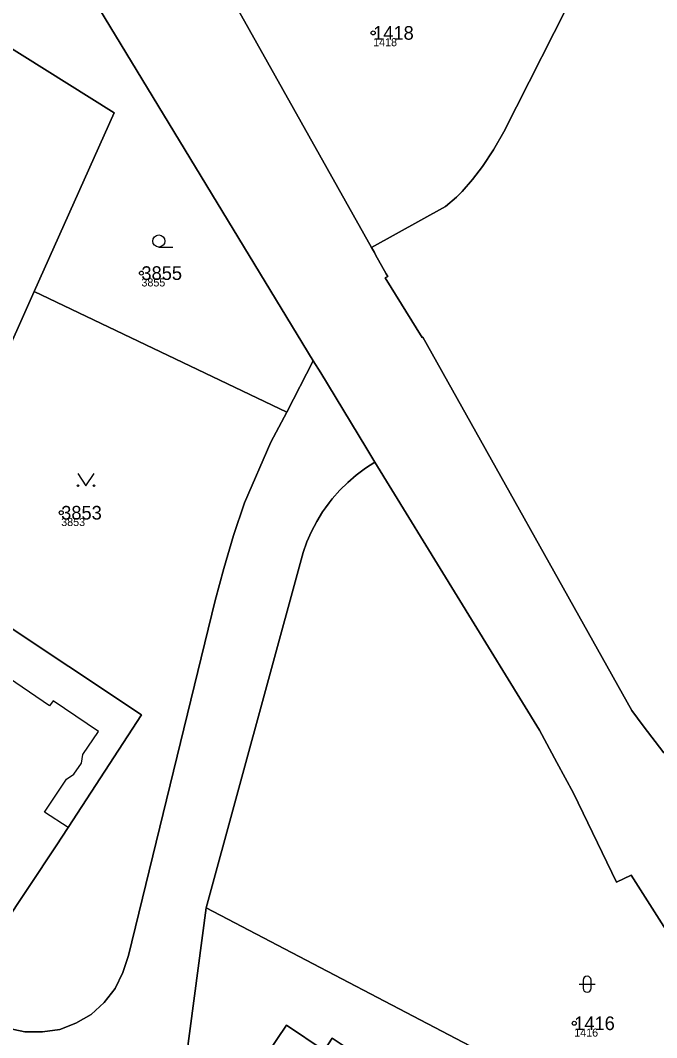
# Model space of a CAD drawing. Extents: x -690132 to -685994, y -975441 to -972444.
# Drawn here: x -688229.2 to -688149.9, y -974661.4 to -974534.7 of the extents above; entities that cross this region are included whole.
import ezdxf

# ---------------------------------------------------------------- set-up
doc = ezdxf.new("R2010")
doc.units = 0
for name, color, linetype in [('Definiční body', 7, 'Continuous'), ('Hranice parcel', 7, 'Continuous'), ('Parcelní čísla', 7, 'Continuous'), ('Polygon budovy', 7, 'Continuous'), ('Polygon parcely', 7, 'Continuous'), ('Vnitřní kresba', 7, 'Continuous'), ('Značky kultur', 7, 'Continuous')]:
    doc.layers.add(name, color=color, linetype=linetype)

msp = doc.modelspace()

# ---------------------------------------------------------------- linework, layer by layer
at = {"layer": 'Definiční body'}
for centre in [(-688185.26, -974536.23), (-688214.14, -974566.16), (-688224.14, -974596.01), (-688160.2, -974659.62)]:
    msp.add_circle(centre, 0.25, dxfattribs=at)
at = {"layer": 'Hranice parcel'}
for p, q in [((-688196.03, -974583.47), (-688227.51, -974568.46)), ((-688196.03, -974583.47), (-688192.72, -974577.08)), ((-688194.35, -974602.34), (-688206.07, -974645.24)), ((-688206.07, -974645.24), (-688210.5, -974678.74)), ((-688167.82, -974665.26), (-688206.07, -974645.24))]:
    msp.add_line(p, q, dxfattribs=at)
for points in [[(-688226.93, -974494.5), (-688226.36, -974494.84), (-688228.12, -974498.25), (-688227.56, -974498.86), (-688228.1, -974504.08), (-688228.16, -974504.63), (-688227.95, -974509.99), (-688227.92, -974510.85), (-688227.07, -974516.99), (-688225.82, -974521.31), (-688223.67, -974525.76), (-688219.35, -974533.29), (-688192.72, -974577.08)], [(-688214, -974502.8), (-688213.74, -974504.74), (-688206.25, -974525.92), (-688185.48, -974562.95)], [(-688185.48, -974562.95), (-688176.26, -974557.84), (-688174.87, -974556.7), (-688174.17, -974555.98), (-688172.87, -974554.48), (-688171.64, -974552.87), (-688170.27, -974550.8), (-688168.96, -974548.55), (-688159.56, -974529.9), (-688160.2, -974529.58)], [(-688227.51, -974568.46), (-688217.55, -974546.21), (-688234.6, -974535.5)], [(-688137.77, -974631.27), (-688139.27, -974630.74), (-688142.11, -974629.76), (-688143.26, -974629.15), (-688145.38, -974628.02), (-688146.53, -974627.41), (-688146.43, -974627.23), (-688149.02, -974625.93), (-688151.61, -974622.56), (-688153.01, -974620.67), (-688179.08, -974574.14), (-688179.17, -974574.19), (-688183.76, -974566.73), (-688183.45, -974566.56), (-688183.62, -974566.26), (-688184.95, -974563.9), (-688185.11, -974563.6), (-688185.48, -974562.95)], [(-688227.51, -974568.46), (-688236.79, -974589.17), (-688246.24, -974584.46), (-688250.35, -974592.63)], [(-688192.72, -974577.08), (-688191.79, -974578.6), (-688186.17, -974587.86), (-688185.03, -974589.73)], [(-688246.03, -974650.73), (-688233.43, -974659.18), (-688232.89, -974659.47), (-688230.82, -974660.22), (-688228.67, -974660.69), (-688226.48, -974660.68), (-688224.32, -974660.38), (-688222.3, -974659.6), (-688220.4, -974658.52), (-688218.77, -974657.02), (-688217.43, -974655.28), (-688216.44, -974653.28), (-688215.74, -974651.18), (-688204.95, -974606.93), (-688203.89, -974602.95), (-688202.67, -974598.84), (-688201.3, -974594.78), (-688198.01, -974587.21), (-688196.03, -974583.47)], [(-688185.03, -974589.73), (-688186.22, -974590.48), (-688187.36, -974591.32), (-688188.43, -974592.23), (-688189.43, -974593.22), (-688190.36, -974594.28), (-688190.75, -974594.76), (-688191.57, -974595.91), (-688192.3, -974597.11), (-688192.95, -974598.36), (-688193.51, -974599.65), (-688193.98, -974600.98), (-688194.35, -974602.34)], [(-688185.03, -974589.73), (-688164.51, -974623.1), (-688162.36, -974627.14), (-688160.29, -974630.96), (-688154.92, -974642.04), (-688153.12, -974641.17), (-688147, -974650.74), (-688144.11, -974656.03), (-688143.04, -974657.52), (-688141.72, -974658.88), (-688139.95, -974660.3), (-688138.04, -974661.53), (-688136.02, -974662.52), (-688077.82, -974683.21), (-688075.88, -974684.07), (-688073.68, -974685.3)], [(-688223.29, -974635.24), (-688214.14, -974621.2), (-688250.39, -974597.11)], [(-688246.03, -974650.73), (-688241.97, -974644.53), (-688241.77, -974644.24), (-688240.37, -974642.09), (-688240.05, -974642.22), (-688231.6, -974647.77), (-688224.78, -974637.53), (-688223.29, -974635.24)], [(-688177.47, -974678.89), (-688189.24, -974676.88), (-688193.95, -974673.72), (-688194.2, -974674.09), (-688197.45, -974671.92), (-688197.2, -974671.55), (-688201.85, -974668.42), (-688196.05, -974659.85), (-688191.36, -974663), (-688190.35, -974661.49), (-688187.14, -974663.63), (-688187.48, -974664.13), (-688185.57, -974665.45), (-688185.21, -974664.91), (-688182.5, -974666.73), (-688177.63, -974666.01)]]:
    msp.add_lwpolyline(points, dxfattribs=at)
at = {"layer": 'Polygon budovy'}
msp.add_lwpolyline([(-688231.6, -974647.77), (-688224.78, -974637.53), (-688223.29, -974635.24), (-688226.23, -974633.31), (-688223.49, -974629.19), (-688222.56, -974628.6), (-688221.63, -974627.21), (-688221.45, -974626.12), (-688219.5, -974623.25), (-688225.16, -974619.44), (-688225.58, -974620.06), (-688231.5, -974616.05)], dxfattribs=at)
msp.add_lwpolyline([(-688196.05, -974659.85), (-688201.85, -974668.42), (-688197.2, -974671.55), (-688197.45, -974671.92), (-688194.2, -974674.09), (-688193.95, -974673.72), (-688189.24, -974676.88), (-688187.37, -974674.06), (-688186.13, -974672.21), (-688184.65, -974669.99), (-688183.95, -974668.95), (-688183.5, -974668.25), (-688186.22, -974666.43), (-688185.57, -974665.45), (-688187.48, -974664.13), (-688187.14, -974663.63), (-688190.35, -974661.49), (-688191.36, -974663)], close=True, dxfattribs=at)
at = {"layer": 'Polygon parcely'}
for points in [[(-688174.87, -974556.7), (-688174.17, -974555.98), (-688172.87, -974554.48), (-688171.64, -974552.87), (-688170.27, -974550.8), (-688168.96, -974548.55), (-688159.56, -974529.9), (-688160.2, -974529.58), (-688166.78, -974526.32), (-688172.24, -974523.91), (-688188.89, -974516.57), (-688191.58, -974515.38), (-688196.43, -974512.57), (-688204.31, -974508), (-688211.75, -974503.7), (-688214, -974502.8), (-688213.74, -974504.74), (-688206.25, -974525.92), (-688185.48, -974562.95), (-688176.26, -974557.84)], [(-688235.32, -974536.94), (-688242.43, -974551.08), (-688246.59, -974559.36), (-688256.6, -974579.3), (-688248.38, -974583.39), (-688252.34, -974591.59), (-688250.35, -974592.63), (-688246.24, -974584.46), (-688236.79, -974589.17), (-688227.51, -974568.46), (-688217.55, -974546.21), (-688234.6, -974535.5)], [(-688172.31, -974669.14), (-688177.63, -974666.01), (-688182.5, -974666.73), (-688185.21, -974664.91), (-688185.57, -974665.45), (-688187.48, -974664.13), (-688187.14, -974663.63), (-688190.35, -974661.49), (-688191.36, -974663), (-688196.05, -974659.85), (-688201.85, -974668.42), (-688197.2, -974671.55), (-688197.45, -974671.92), (-688194.2, -974674.09), (-688193.95, -974673.72), (-688189.24, -974676.88), (-688177.47, -974678.89), (-688172.81, -974672.27)]]:
    msp.add_lwpolyline(points, close=True, dxfattribs=at)
for points in [[(-688134.02, -974533.98), (-688158.05, -974524.54), (-688159.47, -974527.87), (-688160.2, -974529.58), (-688159.56, -974529.9), (-688168.96, -974548.55), (-688170.27, -974550.8), (-688171.64, -974552.87), (-688172.87, -974554.48), (-688174.17, -974555.98), (-688174.87, -974556.7), (-688176.26, -974557.84), (-688185.48, -974562.95), (-688185.11, -974563.6), (-688184.95, -974563.9), (-688183.62, -974566.26), (-688183.45, -974566.56), (-688183.76, -974566.73), (-688179.17, -974574.19), (-688179.08, -974574.14), (-688153.01, -974620.67), (-688151.61, -974622.56), (-688149.02, -974625.93)], [(-688149.02, -974625.93), (-688151.61, -974622.56), (-688153.01, -974620.67), (-688179.08, -974574.14), (-688179.17, -974574.19), (-688183.76, -974566.73), (-688183.45, -974566.56), (-688183.62, -974566.26), (-688184.95, -974563.9), (-688185.11, -974563.6), (-688185.48, -974562.95), (-688206.25, -974525.92)], [(-688244.23, -974528.29), (-688257.52, -974554.15), (-688253.8, -974555.92), (-688246.59, -974559.36), (-688242.43, -974551.08), (-688235.32, -974536.94), (-688234.6, -974535.5), (-688217.55, -974546.21), (-688227.51, -974568.46), (-688196.03, -974583.47), (-688192.72, -974577.08), (-688219.35, -974533.29)], [(-688219.35, -974533.29), (-688192.72, -974577.08), (-688191.79, -974578.6), (-688186.17, -974587.86), (-688185.03, -974589.73), (-688164.51, -974623.1), (-688162.36, -974627.14), (-688160.29, -974630.96), (-688154.92, -974642.04), (-688153.12, -974641.17), (-688147, -974650.74)], [(-688230.82, -974660.22), (-688228.67, -974660.69), (-688226.48, -974660.68), (-688224.32, -974660.38), (-688222.3, -974659.6), (-688220.4, -974658.52), (-688218.77, -974657.02), (-688217.43, -974655.28), (-688216.44, -974653.28), (-688215.74, -974651.18), (-688204.95, -974606.93), (-688203.89, -974602.95), (-688202.67, -974598.84), (-688201.3, -974594.78), (-688198.01, -974587.21), (-688196.03, -974583.47), (-688227.51, -974568.46), (-688236.79, -974589.17)], [(-688210.5, -974678.74), (-688206.07, -974645.24), (-688194.35, -974602.34), (-688193.98, -974600.98), (-688193.51, -974599.65), (-688192.95, -974598.36), (-688192.3, -974597.11), (-688191.57, -974595.91), (-688191.22, -974595.4), (-688190.36, -974594.28), (-688189.43, -974593.22), (-688188.43, -974592.23), (-688187.36, -974591.32), (-688186.22, -974590.48), (-688185.03, -974589.73), (-688186.17, -974587.86), (-688191.79, -974578.6), (-688192.72, -974577.08), (-688196.03, -974583.47), (-688198.01, -974587.21), (-688201.3, -974594.78), (-688202.67, -974598.84), (-688203.89, -974602.95), (-688204.95, -974606.93), (-688215.74, -974651.18), (-688216.44, -974653.28), (-688217.43, -974655.28), (-688218.77, -974657.02), (-688220.4, -974658.52), (-688222.3, -974659.6), (-688224.32, -974660.38), (-688226.48, -974660.68), (-688228.67, -974660.69), (-688230.82, -974660.22)], [(-688147, -974650.74), (-688153.12, -974641.17), (-688154.92, -974642.04), (-688160.29, -974630.96), (-688162.36, -974627.14), (-688164.51, -974623.1), (-688185.03, -974589.73), (-688186.22, -974590.48), (-688187.36, -974591.32), (-688188.43, -974592.23), (-688189.43, -974593.22), (-688190.36, -974594.28), (-688190.75, -974594.76), (-688191.57, -974595.91), (-688192.3, -974597.11), (-688192.95, -974598.36), (-688193.51, -974599.65), (-688193.98, -974600.98), (-688194.35, -974602.34), (-688206.07, -974645.24), (-688167.82, -974665.26)], [(-688250.39, -974597.11), (-688214.14, -974621.2), (-688223.29, -974635.24), (-688224.78, -974637.53), (-688231.6, -974647.77)], [(-688231.6, -974647.77), (-688224.78, -974637.53), (-688223.29, -974635.24), (-688214.14, -974621.2), (-688250.39, -974597.11)], [(-688167.82, -974665.26), (-688206.07, -974645.24), (-688210.5, -974678.74)], [(-688201.85, -974668.42), (-688196.05, -974659.85), (-688191.36, -974663)]]:
    msp.add_lwpolyline(points, dxfattribs=at)
at = {"layer": 'Vnitřní kresba'}
for p, q in [((-688225.58, -974620.06), (-688231.5, -974616.05)), ((-688225.16, -974619.44), (-688225.58, -974620.06)), ((-688219.5, -974623.25), (-688225.16, -974619.44)), ((-688221.45, -974626.12), (-688219.5, -974623.25)), ((-688221.63, -974627.21), (-688221.45, -974626.12)), ((-688222.56, -974628.6), (-688221.63, -974627.21)), ((-688226.23, -974633.31), (-688223.49, -974629.19)), ((-688223.49, -974629.19), (-688222.56, -974628.6)), ((-688223.29, -974635.24), (-688226.23, -974633.31))]:
    msp.add_line(p, q, dxfattribs=at)
at = {"layer": 'Značky kultur'}
for p, q in [((-688211.97, -974562.91), (-688210.22, -974562.91)), ((-688159.59, -974654.75), (-688157.59, -974654.75)), ((-688159.09, -974654.25), (-688159.09, -974655.25)), ((-688158.09, -974655.25), (-688158.09, -974654.25))]:
    msp.add_line(p, q, dxfattribs=at)
msp.add_lwpolyline([(-688222.05, -974591.14), (-688221.05, -974592.64), (-688220.05, -974591.14)], dxfattribs=at)
for centre, radius in [((-688211.97, -974562.16), 0.75), ((-688222.05, -974592.64), 0.1), ((-688220.05, -974592.64), 0.1)]:
    msp.add_circle(centre, radius, dxfattribs=at)
for centre, start, end in [((-688158.59, -974654.25), 0, 180), ((-688158.59, -974655.25), 180, 359.9879)]:
    msp.add_arc(centre, 0.5, start, end, dxfattribs=at)

# ---------------------------------------------------------------- texts
at = {"layer": 'Definiční body'}
for s, p in [('1418', (-688185.26, -974537.89)), ('3855', (-688214.14, -974567.82)), ('3853', (-688224.14, -974597.67)), ('1416', (-688160.2, -974661.28))]:
    msp.add_text(s, height=1, dxfattribs=at).set_placement(p)
at = {"layer": 'Parcelní čísla'}
for s, p in [('1418', (-688185.26, -974537.08)), ('3855', (-688214.14, -974567.01)), ('3853', (-688224.14, -974596.86)), ('1416', (-688160.2, -974660.47))]:
    msp.add_text(s, height=1.7, dxfattribs=at).set_placement(p)

doc.saveas('drawing.dxf')
